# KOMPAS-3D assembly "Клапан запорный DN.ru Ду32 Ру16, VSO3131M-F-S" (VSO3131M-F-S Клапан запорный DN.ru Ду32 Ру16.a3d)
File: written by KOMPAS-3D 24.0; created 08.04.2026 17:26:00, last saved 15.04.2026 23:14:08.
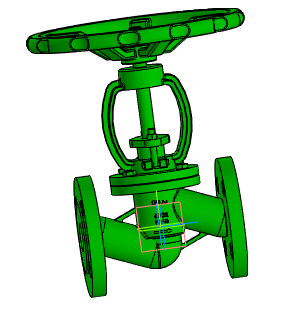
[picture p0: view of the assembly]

Document properties: Автор: R2D2; Полное имя файла: E:\Работа\Зайцев\VSO3131M-F-S Клапан запорный DN.ru Ду15-100 Ру16\DN32\исходные материалы\VSO3131M-F-S Клапан запорный DN.ru Ду32 Ру16.a3d

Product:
- Component [detail]: Корпус  | qty 1  | pos. 1  | Масса: 6.9; Автор: R2D2; source file: Корпус.m3d
- Component [detail]: Клапан запорный DN.ru Ду32 Ру16  | designation VSO1121M-F-S  | qty 1  | pos. 2  | Масса: 7.9; Раздел спецификации: Прочие изделия; Примечание: D090-01945; Автор: R2D2; source file: 2.m3d
- Component [standard]: Hexagon head screw ISO 4017 - М8 x 16  | qty 4  | Масса: 0.012085; Раздел спецификации: Стандартные изделия; Рассекать на разрезах: no
- Part/product: Клапан запорный DN.ru Ду32 Ру16  | designation VSO3131M-F-S
    Масса: 7
    Раздел спецификации: Прочие изделия
    Примечание: D090-02949

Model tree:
1. Массив по концентрической сетке:1  (with: Грань.Элемент вращения:2)  (4 pattern instances)
     Шаг 2 = 360
2. Контекстная связь:1  (with: Ребро.Элемент выдавливания:3, Контекстная связь (Корпус):1, Грань.Элемент вращения:2)  (labels: Грань.Твердое тело1; Грань.Элемент выдавливания:9.Экземпляр ( 1, 2 ))
     Расстояние = -230

Expressions: D090-01945
Referenced files in E:\Работа\Зайцев\VSO3131M-F-S Клапан запорный DN.ru Ду15-100 Ру40\DN32\исходные материалы\: Корпус.m3d, 2.m3d
Referenced files in E:\Работа\Зайцев\VSO3131M-F-S Клапан запорный DN.ru Ду15-100 Ру16\DN32\исходные материалы\: Корпус.m3d, 2.m3d
Referenced files in C:\Program Files\ASCON\KOMPAS-3D v24\Libs\PolynomLib\DATA\vault\Methods\Kompas\3D\: PLib_Bolt_1_ISO_1100.m3d
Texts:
  VSO1121M-F-S
  Hexagon head screw
  BOSimple***PART:17775d1c-e7de-f283-40f0-d40789f7f59e***SHORTLOC:A259_7B16EF33AB1642D2[13;1,25;16;8;-;Undefined]
  Программные изделия  и базы данных
  VSO3131M-F-S
  VSO1121M-F-S Клапан запорный DN.ru Ду32 Ру16
  Hexagon head screw ISO 4017 - М8 x 16 (1)
  hole1
  hole2
  Hexagon head screw ISO 4017 - М8 x 16 (2)
  Hexagon head screw ISO 4017 - М8 x 16 (3)
  Hexagon head screw ISO 4017 - М8 x 16 (4)
  Ось Y.Начало координат
  Плоскость XY.Начало координат
  Плоскость ZX.Начало координат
